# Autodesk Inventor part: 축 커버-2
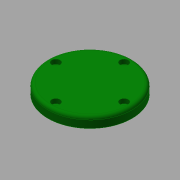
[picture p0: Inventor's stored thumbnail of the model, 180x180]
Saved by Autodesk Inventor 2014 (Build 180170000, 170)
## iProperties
Created: 2015-10
Part Number: 축 커버-2
Document SubType Name: Modeling
Designer: mdu
Density: 7.86 g/cm^3
Material: 강철, 연강
Appearance: Dark Green
Mass: 403.237 g
Surface Area: 134.748 cm^2
Volume: 51.3024 cm^3
Author: mdu
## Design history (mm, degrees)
sketch "스케치1"
  geometry: C1 r 40 at (0, 0) reference; C2 r 26 at (0, 0) reference; 1 further point
  node "참조1"
  node "참조2"
extrude "돌출1" new body sketch "스케치1" distance "d0" = 10; taper "d1" = 0 deg
extrude "돌출2" join sketch "스케치1" distance "d2" = 3; taper "d3" = 0 deg
sketch "스케치2"
  geometry: C1 r 20 at (0, 0); 1 further point
  constraints: 1 centre point, 1 coincident
  dimensions: "d13" = 40 diameter of C1
extrude "돌출3" cut sketch "스케치2" distance "d14" = 3; taper "d15" = 0 deg
sketch "스케치3"
  geometry: C1 r 1.621 at (0, 32.5) reference; 1 further point
hole "구멍2" sketch "스케치3" at (0, 32.5) diameter "d16" = 4.5; stored, may be unused: countersink angle "d20" = 90 deg, drill point angle "d22" = 118 deg; dims "d17" = 6, "d18" = 8, "d19" = 4.4, "d21" = 8
fillet "모깎기1" dims "d26" = 3, "d27" = 0.3
chamfer "모따기1" distance "d28" = 1; stored, may be unused: second distance "d29" = 2, angle "d30" = 45 deg
node "솔리드1"
pattern_circular "원형 패턴1" dims angle "d24" = 360 deg
node "참조3"
